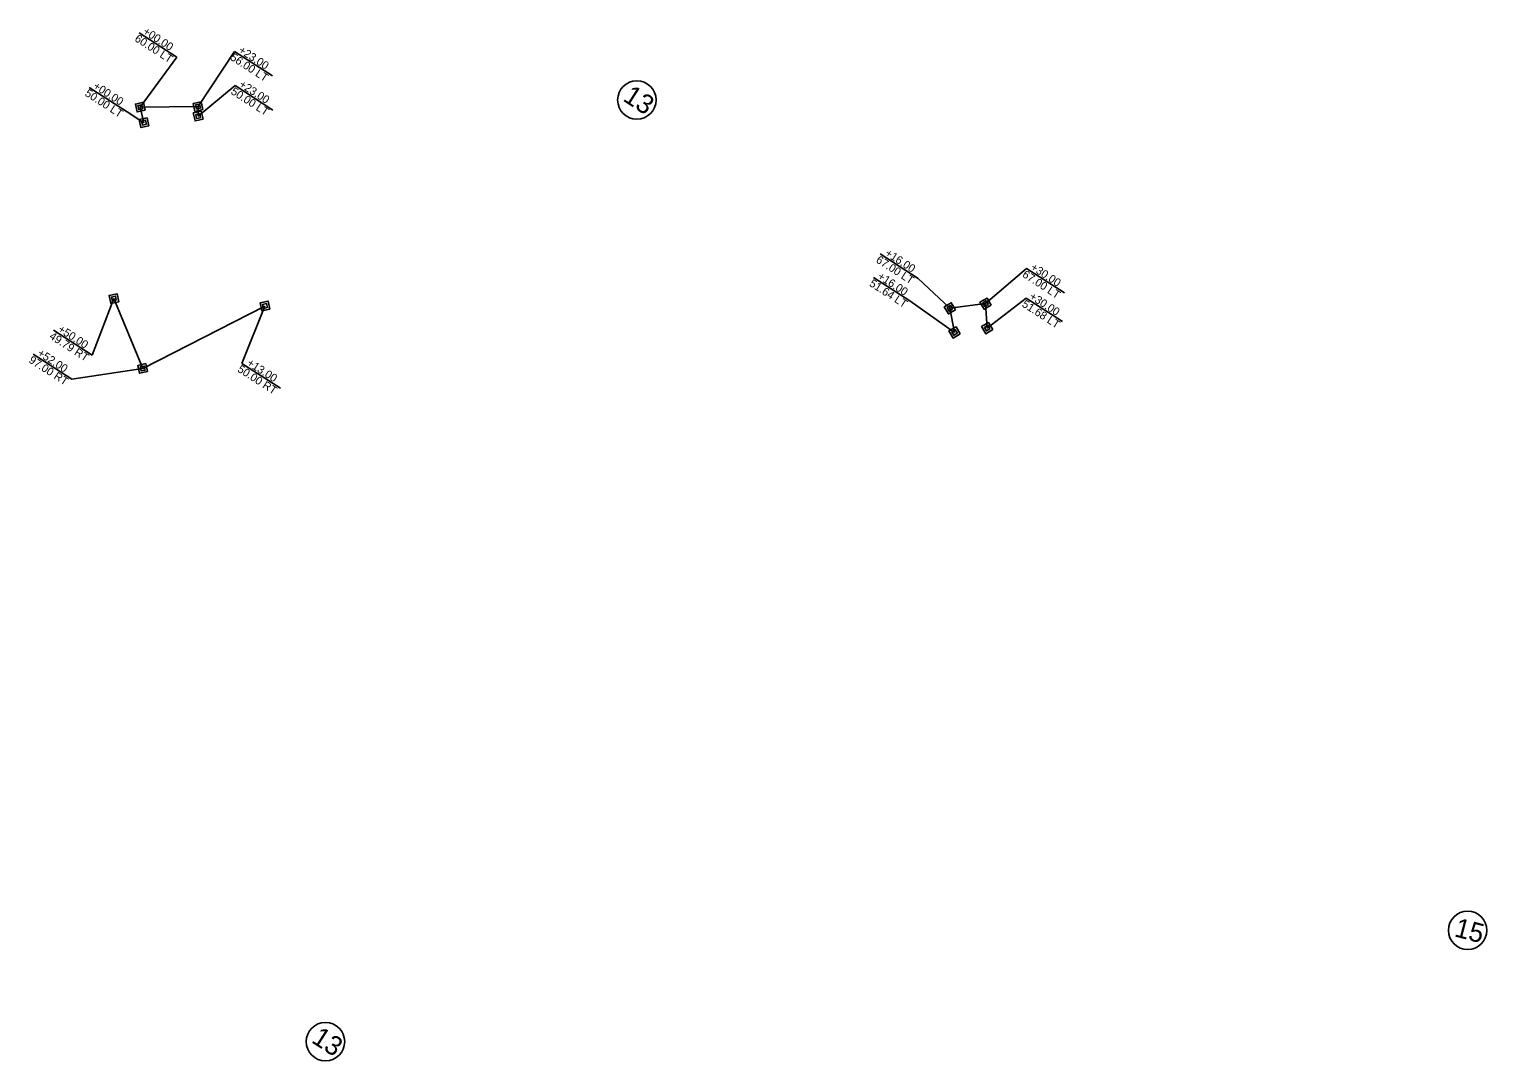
# Model space of a CAD drawing. Extents: x 1002576 to 1014655, y 551673 to 557994.
# Drawn here: x 1006906 to 1007817, y 551806 to 552450 of the extents above; entities that cross this region are included whole.
import ezdxf

# ---------------------------------------------------------------- set-up
doc = ezdxf.new("R2010")
doc.units = 0
for name, color, linetype in [('Exist Building', 7, 'Continuous'), ('Exist Hydro Stream or Body of Water', 7, 'Continuous'), ('Exist Roads EOP Text', 7, 'Continuous'), ('Exist Structure Major Deck Tunnel Box Culvert', 7, 'Continuous'), ('Exist Utilities Power Pole CELL', 7, 'Continuous')]:
    doc.layers.add(name, color=color, linetype=linetype)

msp = doc.modelspace()

# ---------------------------------------------------------------- linework, layer by layer
at = {"layer": 'Exist Building'}
for p, q in [((1006975.61, 552401.72), (1007011.71, 552402.11)), ((1006977.92, 552391.99), (1006975.61, 552401.72)), ((1007011.71, 552402.11), (1007011.76, 552396.11)), ((1006959.13, 552282.16), (1006977.13, 552238.48)), ((1006977.13, 552238.48), (1007053.51, 552277.51)), ((1007481.27, 552276.06), (1007503.59, 552278.98)), ((1007484.23, 552260.99), (1007481.27, 552276.06)), ((1007504.61, 552263.69), (1007503.59, 552278.98))]:
    msp.add_line(p, q, dxfattribs=at)
at = {"layer": 'Exist Hydro Stream or Body of Water'}
for p, q in [((1006975.61, 552401.72), (1006975.61, 552401.72)), ((1007011.71, 552402.11), (1007011.71, 552402.11)), ((1007011.76, 552396.11), (1007011.76, 552396.11)), ((1006977.92, 552391.99), (1006977.92, 552391.99)), ((1006959.13, 552282.16), (1006959.13, 552282.16)), ((1007053.51, 552277.51), (1007053.51, 552277.51)), ((1007481.27, 552276.06), (1007481.27, 552276.06)), ((1007503.59, 552278.98), (1007503.59, 552278.98)), ((1007484.23, 552260.99), (1007484.23, 552260.99)), ((1007504.61, 552263.69), (1007504.61, 552263.69)), ((1006977.13, 552238.48), (1006977.13, 552238.48))]:
    msp.add_line(p, q, dxfattribs=at)
at = {"layer": 'Exist Roads EOP Text'}
for p, q in [((1006998.45, 552432.96), (1006974.82, 552448.2)), ((1007058.13, 552421.22), (1007034.51, 552436.47)), ((1006967.36, 552398.8), (1006943.73, 552414.04)), ((1007058.51, 552399.9), (1007034.88, 552415.14)), ((1007461.47, 552294.76), (1007437.84, 552310)), ((1007456.31, 552280.66), (1007433.69, 552295.25)), ((1007552.86, 552285.64), (1007529.24, 552300.88)), ((1007551.65, 552267.76), (1007529.02, 552282.35)), ((1006945.6, 552246.78), (1006921.48, 552262.34)), ((1006932.78, 552231.85), (1006908.66, 552247.41)), ((1007063.13, 552226.14), (1007039.01, 552241.7))]:
    msp.add_line(p, q, dxfattribs=at)
for points in [[(1006998.45, 552432.96), (1006975.61, 552401.72)], [(1007034.51, 552436.47), (1007011.71, 552402.11)], [(1007034.88, 552415.14), (1007011.76, 552396.11)], [(1006967.36, 552398.8), (1006977.92, 552391.99)], [(1007461.47, 552294.76), (1007481.27, 552276.06)], [(1007529.24, 552300.88), (1007503.59, 552278.98)], [(1006945.6, 552246.78), (1006959.13, 552282.16)], [(1007039.01, 552241.7), (1007053.51, 552277.51)], [(1007456.31, 552280.66), (1007484.23, 552260.99)], [(1007529.02, 552282.35), (1007504.61, 552263.69)], [(1006932.78, 552231.85), (1006977.13, 552238.48)]]:
    msp.add_lwpolyline(points, dxfattribs=at)
at = {"layer": 'Exist Structure Major Deck Tunnel Box Culvert'}
for points in [[(1006978.64, 552399.77), (1006973.66, 552398.7), (1006972.59, 552403.67), (1006977.56, 552404.75)], [(1006977.12, 552400.75), (1006974.64, 552400.21), (1006974.1, 552402.7), (1006976.59, 552403.24)], [(1007014.73, 552400.15), (1007009.75, 552399.08), (1007008.68, 552404.06), (1007013.66, 552405.13)], [(1007013.22, 552401.13), (1007010.73, 552400.59), (1007010.19, 552403.08), (1007012.68, 552403.62)], [(1006980.94, 552390.04), (1006975.97, 552388.97), (1006974.89, 552393.94), (1006979.87, 552395.02)], [(1006979.43, 552391.02), (1006976.94, 552390.48), (1006976.4, 552392.97), (1006978.89, 552393.5)], [(1007014.79, 552394.15), (1007009.81, 552393.08), (1007008.74, 552398.06), (1007013.71, 552399.13)], [(1007013.27, 552395.13), (1007010.79, 552394.59), (1007010.25, 552397.08), (1007012.74, 552397.62)], [(1006962.16, 552280.21), (1006957.18, 552279.13), (1006956.11, 552284.11), (1006961.08, 552285.18)], [(1006960.64, 552281.18), (1006958.16, 552280.65), (1006957.62, 552283.13), (1006960.11, 552283.67)], [(1007056.53, 552275.56), (1007051.55, 552274.49), (1007050.48, 552279.46), (1007055.46, 552280.54)], [(1007055.02, 552276.54), (1007052.53, 552276), (1007051.99, 552278.49), (1007054.48, 552279.02)], [(1007484.75, 552275.15), (1007480.36, 552272.58), (1007477.79, 552276.97), (1007482.18, 552279.55)], [(1007483.01, 552275.61), (1007480.81, 552274.32), (1007479.53, 552276.52), (1007481.72, 552277.8)], [(1007507.07, 552278.07), (1007502.68, 552275.5), (1007500.11, 552279.9), (1007504.5, 552282.47)], [(1007505.33, 552278.53), (1007503.13, 552277.24), (1007501.85, 552279.44), (1007504.05, 552280.73)], [(1007508.09, 552262.78), (1007503.7, 552260.21), (1007501.13, 552264.61), (1007505.52, 552267.18)], [(1007506.35, 552263.24), (1007504.15, 552261.95), (1007502.87, 552264.15), (1007505.06, 552265.44)], [(1007487.71, 552260.08), (1007483.31, 552257.51), (1007480.74, 552261.9), (1007485.14, 552264.47)], [(1007485.97, 552260.53), (1007483.77, 552259.25), (1007482.49, 552261.45), (1007484.68, 552262.73)], [(1006980.15, 552236.53), (1006975.18, 552235.46), (1006974.1, 552240.43), (1006979.08, 552241.51)], [(1006978.64, 552237.51), (1006976.15, 552236.97), (1006975.62, 552239.46), (1006978.1, 552239.99)]]:
    msp.add_lwpolyline(points, close=True, dxfattribs=at)
at = {"layer": 'Exist Utilities Power Pole CELL'}
for p, q in [((1007285.78, 552406.19), (1007285.78, 552406.19)), ((1007804.7, 551887.56), (1007804.7, 551887.56)), ((1007091.28, 551818.05), (1007091.28, 551818.05))]:
    msp.add_line(p, q, dxfattribs=at)
for centre in [(1007285.78, 552406.19), (1007804.7, 551887.56), (1007091.28, 551818.05)]:
    msp.add_circle(centre, 12, dxfattribs=at)

# ---------------------------------------------------------------- texts
at = {"layer": 'Exist Roads EOP Text'}
for s, p in [('60.00 LT', (1006971.67, 552443.35)), ('+00.00', (1006976.83, 552447.83)), ('+23.00', (1007036.51, 552436.1)), ('56.00 LT', (1007031.36, 552431.62)), ('50.00 LT', (1006940.58, 552409.2)), ('+00.00', (1006945.74, 552413.67)), ('50.00 LT', (1007031.73, 552410.3)), ('+23.00', (1007036.89, 552414.77)), ('+16.00', (1007440.35, 552309.31)), ('67.00 LT', (1007434.69, 552305.16)), ('+30.00', (1007531.24, 552300.51)), ('51.64 LT', (1007430.54, 552290.41)), ('+16.00', (1007435.7, 552294.88)), ('67.00 LT', (1007526.09, 552296.04)), ('+30.00', (1007530.53, 552282.3)), ('51.68 LT', (1007525.87, 552277.51)), ('49.79 RT', (1006918.33, 552257.5)), ('+50.00', (1006923.73, 552261.81)), ('+52.00', (1006910.92, 552246.88)), ('97.00 RT', (1006905.51, 552242.57)), ('50.00 RT', (1007035.86, 552236.86)), ('+13.00', (1007041.77, 552240.84))]:
    msp.add_text(s, height=5, rotation=327.17665, dxfattribs=at).set_placement(p)
at = {"layer": 'Exist Utilities Power Pole CELL'}
for s, rotation, p in [('13', 327.17665, (1007276.43, 552406.09)), ('15', 345.33435, (1007795.82, 551883.95)), ('13', 327.17665, (1007081.92, 551817.95))]:
    msp.add_text(s, height=12, rotation=rotation, dxfattribs=at).set_placement(p)

doc.saveas('drawing.dxf')
